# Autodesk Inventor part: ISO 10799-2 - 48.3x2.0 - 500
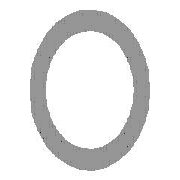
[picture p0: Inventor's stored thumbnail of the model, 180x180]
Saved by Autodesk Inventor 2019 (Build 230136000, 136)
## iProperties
IsCustomPart: 1
Created: 2018-01
Part Number: ISO 10799-2 - 48.3x2.0 - 500
Material: Acier, doux
Description: Aciers de construction - Coupes creuses profilées formées à froid, soudées
Document SubType Name: Modeling
Standard: ISO
Designer: Fabian Perrée
Standard Revision: First edition 2011-09-15
Standards Organization: ISO
Language: fr-FR
Size Designation: 48.3x2.0
Categories: <MemberInstance><Categories><Category DisplayName="Profilés" InternalName="089c4875-fa83-4c05-b084-43b9cc11f5ed" Mnemonic="GRDR"><CategoryParameter DisplayName=
Stock Number: 48.3x2.0
Density: 7.85 g/cm^3
Appearance: Semi-poli
Mass: 1065.61 g
Surface Area: 1369.22 cm^2
Volume: 135.746 cm^3
_CCFamilyMember: 14
_CCFamilyDisplayName: ISO 10799-2 (Profils creux circulaires - Formés à froid) - Aciers de construction - Coupes creuses profilées formées à froid, soudées
_FrameMemberDoc: Frame Member File
_Version: 15.0.0
_GetPNFromCC: 1
G_L: 500,000 mm
G_W: 48,300 mm
G_H: 48,300 mm
+2D9F7695-4A5C-463C-B0A0-518010C687B0+DETAILDECOUPE1: Grugeage
+B9C4214B-9881-441A-A920-C25C553D1DF1+DETAILDECOUPE2: Grugeage
Author: Fabian Perrée
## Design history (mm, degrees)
node "Plan de départ"
node "Plan de fin"
sketch "Esquisse"
  geometry: C1 r 22.15 at (0, 0); C2 r 24.15 at (0, 0); 2 further points
  constraints: 3 coincident, 2 centre point
  dimensions: "d0" = 48.3 diameter of C2 (= G_H); "d1" = 2 radial gap between concentric circles of C2 C1 (= G_T)
extrude "Corps" new body sketch "Esquisse" stored distance "d2" = 500 (= G_L); taper "d3" = 0 deg
node "Driven Length"
  sketch "Sketch3"
    geometry: L1 (0, 0)-(10, 0) reference
    constraints: 2 end point, 1 horizontal
  workplane "Work Plane3"
  sketch "Sketch4"
    geometry: L1 (-2, 0)-(12, 0) reference; L2 (-2, 500)-(12, 500) reference
    dimensions: "d7" = 500 distance between parallel lines of L1 L2 (derived)
body "Solid1"
feature "Sculpter1"
feature "Combiner1"
feature "Sculpter3"
feature "Combiner3"
body "Srf29"
body "Srf30"
node "Solide11"
body "Srf32"
body "Srf33"
node "Solide12"
feature "Surface1"
body "Srf28"
feature "Carreau délimité19" dims "d44" = 5, "d45" = 0
feature "Carreau délimité20" dims "d46" = 5, "d47" = 0
feature "Surface3"
body "Srf31"
feature "Carreau délimité21" dims "d48" = 5, "d49" = 0
feature "Carreau délimité22" dims "d50" = 5, "d51" = 0
other parameters: "G_H" = 48.3 [user parameter; used in 1 equation term], "G_T" = 2 [user parameter; used in 1 equation term], "G_L" = 500 (= d7) [user parameter; used in 1 equation term], "G_OFFSET_START" = 0 [user parameter; used in 1 equation term], "G_OFFSET_END" = 0 [user parameter; used in 1 equation term], "d4" = 0 (computed from G_OFFSET_START), "d5" = 500 (= G_OFFSET_END + B_L), "B_L" = 500 [user parameter; used in 1 equation term], "d6" = 90 deg, "MAS" = 0.228 [user parameter]
